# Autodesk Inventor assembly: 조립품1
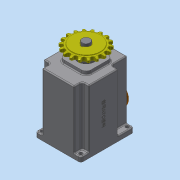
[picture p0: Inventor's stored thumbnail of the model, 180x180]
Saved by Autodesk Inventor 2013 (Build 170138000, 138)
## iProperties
Created: 2017-12
Part Number: 조립품1
Document SubType Name: Assembly
Designer: dgall
Author: dgall
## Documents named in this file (17)
- C:\Users\dgall\Desktop\371207V1017\조립품1.iam
- C:\Users\dgall\Desktop\371207V1017\본체.ipt
- C:\Users\dgall\Desktop\371207V1017\오일 실 8 22 7.ipt
- C:\Users\dgall\Desktop\371207V1017\커버.ipt
- C:\Users\dgall\Desktop\371207V1017\베어링 608.ipt
- C:\Users\dgall\Desktop\371207V1017\볼트 M4 x 10.ipt
- C:\Users\dgall\Desktop\371207V1017\메인축.ipt
- C:\Users\dgall\Desktop\371207V1017\서브축.ipt
- C:\Users\dgall\Desktop\371207V1017\베어링 6003.ipt
- C:\Users\dgall\Desktop\371207V1017\키 5 x 5 x 18.ipt
- C:\Users\dgall\Desktop\371207V1017\오일 실 17 32 8.ipt
- C:\Users\dgall\Desktop\371207V1017\스프로킷.ipt
- C:\Users\dgall\Desktop\371207V1017\멈춤나사 M3x8.ipt
- C:\Users\dgall\Desktop\371207V1017\상부 캡.ipt
- C:\Users\dgall\Desktop\371207V1017\슬라이더.ipt
- C:\Users\dgall\Desktop\371207V1017\가변스프링.ipt
- C:\Users\dgall\Desktop\371207V1017\부시.ipt
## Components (1 placed, 1 different names)
1. 가변스프링:1
